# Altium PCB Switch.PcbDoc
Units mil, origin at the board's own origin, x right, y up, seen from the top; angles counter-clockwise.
Board outline 275.59 x 236.22 mil, 2 copper layers (Top Layer, Bottom Layer); 2 components, 2 nets, 8 pads, 6 vias.
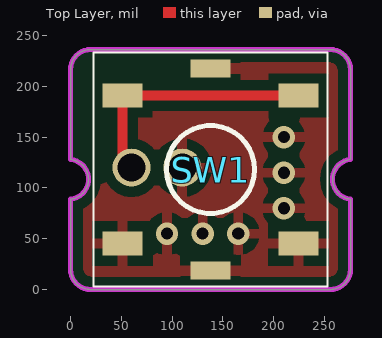
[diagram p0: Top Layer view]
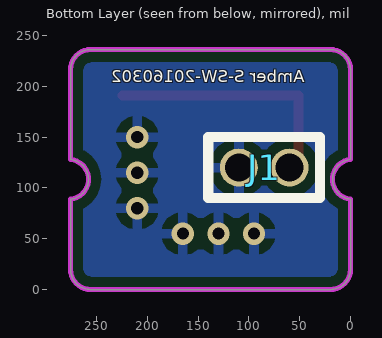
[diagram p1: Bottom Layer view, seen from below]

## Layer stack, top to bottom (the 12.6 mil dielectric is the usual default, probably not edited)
Top Layer: signal copper 1.4
Dielectric: dielectric 12.6, FR-4, Dk 4.8
Bottom Layer: signal copper 1.4

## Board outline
0,19.69 0,88.88 ccw(c-1.97,108.47) 0,128.05 0,216.54 cw(c19.68,216.54) 19.68,236.22 255.91,236.22 cw(c255.91,216.54) 275.59,216.54 275.59,128.05 ccw(c277.56,108.47) 275.59,88.88 275.59,19.69 cw(c255.91,19.69) 255.91,0 19.68,0 cw(c19.68,19.69)

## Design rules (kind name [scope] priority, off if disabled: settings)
Clearance [All] p1: gap=10
PolygonConnect [All] p1: connectstyle=Relief reliefconductorwidth=10 reliefentries=4 polygonreliefangle="90 Angle"
RoutingVias [All] p1: holewidth=28 width=50 viastyle="Through Hole" minholewidth=28 minwidth=50 maxholewidth=28 maxwidth=50
SilkscreenOverComponentPads [All] p1: minsilkscreentomaskgap=10
SolderMaskExpansion [All] p1: expansion=4
Width [All] p1: maxlimit=10 minlimit=10 preferedwidth=10
27 further rules are at their usual default settings.

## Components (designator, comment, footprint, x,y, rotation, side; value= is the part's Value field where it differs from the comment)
J1 "Debug" Debug-2Pin 85,120 r0 bottom
SW1 "Switch_1" EVQPLD 137.8,118.11 r270 top

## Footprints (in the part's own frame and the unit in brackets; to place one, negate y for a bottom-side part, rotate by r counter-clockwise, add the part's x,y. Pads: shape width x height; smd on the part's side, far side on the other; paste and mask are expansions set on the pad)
Debug-2Pin [mm]
  round 0.95 hole 0.7: 1(-0.635,0) 2(0.635,0)
  silkscreen extent -1.4,-0.76 1.4,0.76, body extent -1.21,-0.58 1.21,0.58
EVQPLD [mm]
  rect 0.6x1 smd: A(-1.85,2.2) A'(-1.85,-2.2) B(1.85,2.2) B'(1.85,-2.2)
  rect 0.45x1 smd: C(-2.525,0) C'(2.525,0)
  silkscreen extent -2.92,-2.92 2.92,2.92

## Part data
J1: library part Debug_1, "³§¼Ò£"
SW1: "³§¼Ò£ºË"

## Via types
v1: diameter 22, hole 12, Top Layer to Bottom Layer, tented both sides, 6 vias

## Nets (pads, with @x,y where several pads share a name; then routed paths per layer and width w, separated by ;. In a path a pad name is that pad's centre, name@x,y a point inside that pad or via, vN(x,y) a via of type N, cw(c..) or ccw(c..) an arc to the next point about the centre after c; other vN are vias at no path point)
GND: J1.2 SW1.B SW1.B' SW1.C SW1.C'
  other v1: 95,55 130,55 165,55 210,80 210,115 210,150
SWITCH_KEY: J1.1 SW1.A SW1.A' | length 247.8
  Top Layer w10: J1.1 51.18,128.82 SW1.A' SW1.A

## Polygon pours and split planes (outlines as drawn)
GND on Top Layer "Bottom Layer-No Net" (solid, remove dead copper, pour order 2): 0,236.22 275.59,236.22 275.59,0 0,0 0,236.22
GND on Bottom Layer "Bottom Layer-No Net" (solid, remove dead copper, pour order 4): 0,236.22 275.59,236.22 275.59,0 0,0 0,236.22

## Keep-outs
Keep-Out Layer:
  the board outline again, w5

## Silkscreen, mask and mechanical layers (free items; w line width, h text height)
Top Overlay:
  circle w5: c137.8,118.11 r43.31
Bottom Overlay:
  text "Amber S-SW-20160302" at 45,200 h20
